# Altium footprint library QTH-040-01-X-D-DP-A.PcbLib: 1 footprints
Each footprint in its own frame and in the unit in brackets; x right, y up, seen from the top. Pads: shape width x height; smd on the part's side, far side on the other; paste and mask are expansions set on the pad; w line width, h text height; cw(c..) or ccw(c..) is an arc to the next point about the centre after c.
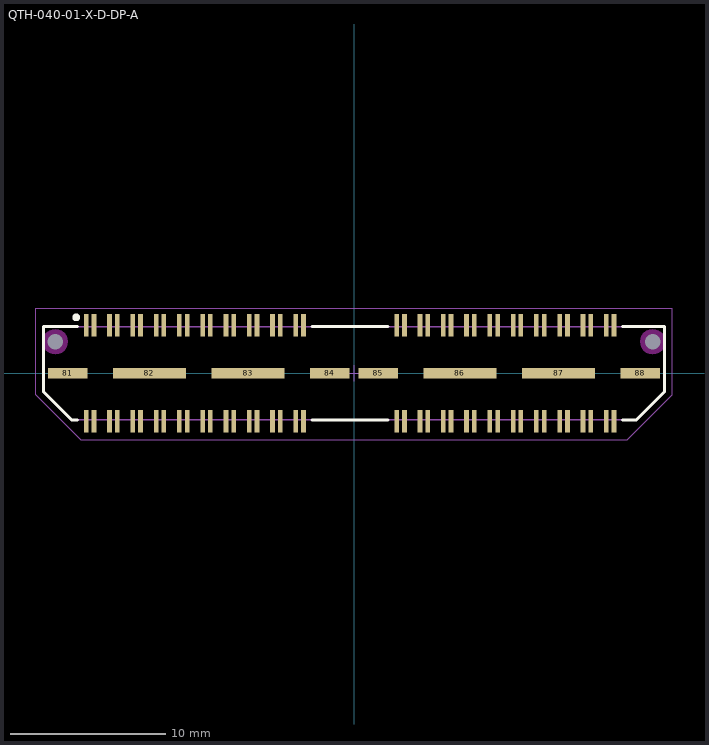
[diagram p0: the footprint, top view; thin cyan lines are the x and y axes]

## QTH-040-01-X-D-DP-A [mm] "0.50mm pitch, 80 pin, high speed terminal strip; differential"
height 4.27
pads (90):
  rect 0.3x1.45 smd mask+0: 1(-17.25,3.09) 2(-17.25,-3.09) 3(-16.75,3.09) 4(-16.75,-3.09) 5(-15.75,3.09) 6(-15.75,-3.09) 7(-15.25,3.09) 8(-15.25,-3.09) 9(-14.25,3.09) 10(-14.25,-3.09) 11(-13.75,3.09) 12(-13.75,-3.09) 13(-12.75,3.09) 14(-12.75,-3.09) 15(-12.25,3.09) 16(-12.25,-3.09) 17(-11.25,3.09) 18(-11.25,-3.09) 19(-10.75,3.09) 20(-10.75,-3.09) 21(-9.75,3.09) 22(-9.75,-3.09) 23(-9.25,3.09) 24(-9.25,-3.09) 25(-8.25,3.09) 26(-8.25,-3.09) 27(-7.75,3.09) 28(-7.75,-3.09) 29(-6.75,3.09) 30(-6.75,-3.09) 31(-6.25,3.09) 32(-6.25,-3.09) 33(-5.25,3.09) 34(-5.25,-3.09) 35(-4.75,3.09) 36(-4.75,-3.09) 37(-3.75,3.09) 38(-3.75,-3.09) 39(-3.25,3.09) 40(-3.25,-3.09) 41(2.75,3.09) 42(2.75,-3.09) 43(3.25,3.09) 44(3.25,-3.09) 45(4.25,3.09) 46(4.25,-3.09) 47(4.75,3.09) 48(4.75,-3.09) 49(5.75,3.09) 50(5.75,-3.09) 51(6.25,3.09) 52(6.25,-3.09) 53(7.25,3.09) 54(7.25,-3.09) 55(7.75,3.09) 56(7.75,-3.09) 57(8.75,3.09) 58(8.75,-3.09) 59(9.25,3.09) 60(9.25,-3.09) 61(10.25,3.09) 62(10.25,-3.09) 63(10.75,3.09) 64(10.75,-3.09) 65(11.75,3.09) 66(11.75,-3.09) 67(12.25,3.09) 68(12.25,-3.09) 69(13.25,3.09) 70(13.25,-3.09) 71(13.75,3.09) 72(13.75,-3.09) 73(14.75,3.09) 74(14.75,-3.09) 75(15.25,3.09) 76(15.25,-3.09) 77(16.25,3.09) 78(16.25,-3.09) 79(16.75,3.09) 80(16.75,-3.09)
  rect 2.55x0.65 smd mask+0: 81(-18.445,0) 84(-1.555,0) 85(1.555,0) 88(18.445,0)
  rect 4.7x0.65 smd mask+0: 82(-13.175,0) 83(-6.825,0) 86(6.825,0) 87(13.175,0)
  round 0.5 hole 1 unplated mask+0: 89(-19.24,2.03) 90(19.24,2.03)
Top Overlay:
  circle w0.25: c-17.9,3.6 r0.125
  lines w0.2: -17.8,-3 -18.2,-3 -20,-1.2 -20,3 -17.8,3 ; -2.7,-3 2.2,-3 ; -2.7,3 2.2,3 ; 17.3,-3 18.2,-3 20,-1.2 20,3 17.3,3
Keep-Out Layer:
  pour cut-out: 20.047,2.03 20.019,2.239 19.939,2.433 19.811,2.601 19.643,2.729 19.449,2.809 19.24,2.837 19.031,2.809 18.837,2.729 18.669,2.601 18.541,2.433 18.461,2.239 18.433,2.03 18.461,1.821 18.541,1.627 18.669,1.459 18.837,1.331 19.031,1.251 19.24,1.223 19.449,1.251 19.643,1.331 19.811,1.459 19.939,1.627 20.019,1.821
  pour cut-out: -18.433,2.03 -18.461,2.239 -18.541,2.433 -18.669,2.601 -18.837,2.729 -19.031,2.809 -19.24,2.837 -19.449,2.809 -19.643,2.729 -19.811,2.601 -19.939,2.433 -20.019,2.239 -20.047,2.03 -20.019,1.821 -19.939,1.627 -19.811,1.459 -19.643,1.331 -19.449,1.251 -19.24,1.223 -19.031,1.251 -18.837,1.331 -18.669,1.459 -18.541,1.627 -18.461,1.821
Mechanical 12:
  lines w0.001: -20.05,-1.2 -20.05,3 19.95,3 19.95,-1.185 18.136,-3 -18.25,-3 -20.05,-1.2
Mechanical 13:
  lines w0.1: -20,-1.2 -20,3 20,3 20,-1.185 18.186,-3 -18.2,-3 -20,-1.2
  text ".Designator" at 0,0 h1.52
Mechanical 15:
  lines w0.05: -0.5,0 0.5,0 ; 0,-0.5 0,0.5 ; -20.498,-1.397 -20.498,4.2 20.498,4.2 20.498,-1.397 17.6,-4.297 -17.597,-4.297 -20.498,-1.397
